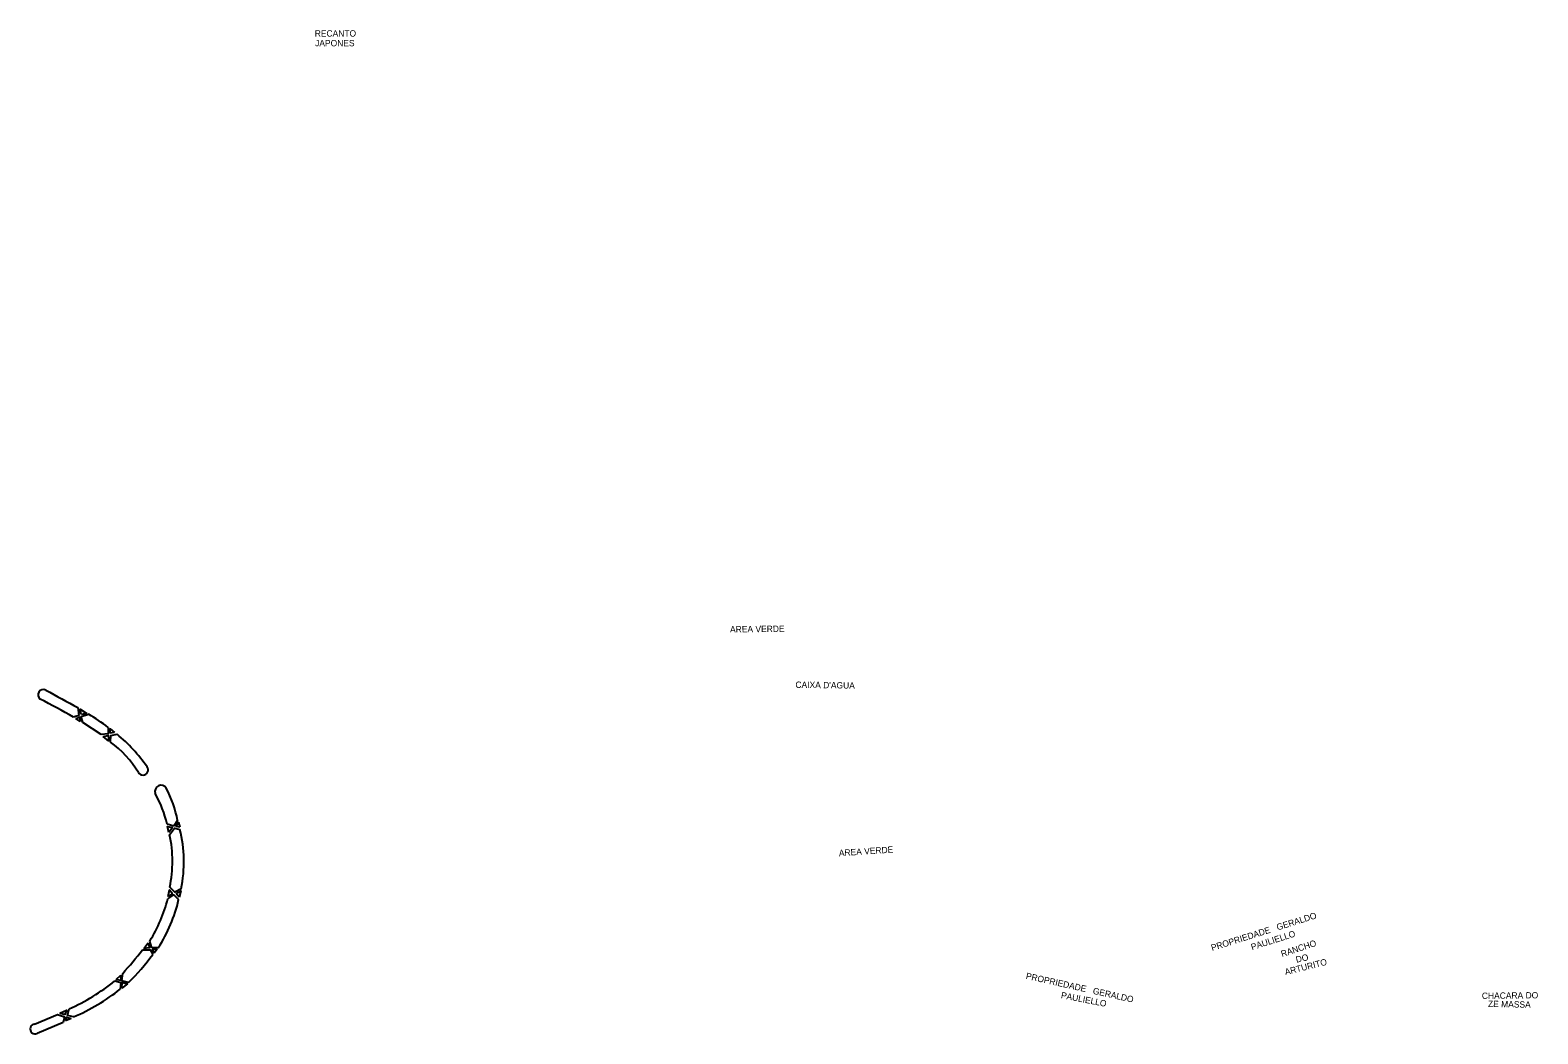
# Model space of a CAD drawing. Extents: x 325899 to 363134, y 7578590 to 7592502.
# Drawn here: x 338922 to 339876, y 7590627 to 7591261 of the extents above; entities that cross this region are included whole.
import ezdxf

# ---------------------------------------------------------------- set-up
doc = ezdxf.new("R2010")
doc.units = 0
doc.layers.add('EDIFIDENTIF', color=7, linetype='Continuous')
doc.layers.add('EDIFOBRAEXIS', color=7, linetype='Continuous')

msp = doc.modelspace()

# ---------------------------------------------------------------- linework, layer by layer
at = {"layer": 'EDIFOBRAEXIS'}
for points in [[(338952.27, 7590832.86), (338952.92, 7590827.89)], [(338954.34, 7590828.56), (338953.68, 7590831.88), (338957.86, 7590829.15)], [(338952.92, 7590827.89), (338949.55, 7590826.85)], [(338951.08, 7590825.9), (338953.39, 7590826.75), (338953.76, 7590824.14)], [(338953.76, 7590824.14), (338951.08, 7590825.9)], [(338957.86, 7590829.15), (338954.34, 7590828.56)], [(338955.34, 7590823.49), (338954.47, 7590827.17), (338958.98, 7590828.6)], [(338967.12, 7590815.74), (338955.34, 7590823.49)], [(338971.4, 7590820.27), (338971.4, 7590816.21), (338967.12, 7590815.74)], [(338968.27, 7590814.51), (338971.36, 7590815.09), (338971.79, 7590811.69)], [(338971.79, 7590811.69), (338968.27, 7590814.51)], [(338972.75, 7590816.6), (338972.62, 7590819.44), (338975.51, 7590817.05)], [(338975.51, 7590817.05), (338972.75, 7590816.6)], [(338972.87, 7590811.07), (338973.11, 7590815.21), (338977.06, 7590815.97)], [(339013.06, 7590757.84), (339008.76, 7590759.02)], [(339009.84, 7590753.86), (339008.95, 7590757.63), (339012.13, 7590756.92)], [(339012.13, 7590756.92), (339009.84, 7590753.86)], [(339010.33, 7590752.44), (339013.47, 7590756.62), (339016.8, 7590755.81)], [(339015.39, 7590761.54), (339013.06, 7590757.84)], [(339014.33, 7590757.72), (339015.93, 7590760.25), (339016.69, 7590757.23)], [(339016.69, 7590757.23), (339014.33, 7590757.72)], [(339009.49, 7590713.46), (339010.17, 7590717.65), (339012.14, 7590715.23)], [(339012.14, 7590715.23), (339009.49, 7590713.46)], [(339017.6, 7590718.24), (339013.56, 7590716.05), (339010.44, 7590719.23)], [(339014.5, 7590715.32), (339017.38, 7590716.92), (339016.45, 7590712.98)], [(339016.45, 7590712.98), (339014.5, 7590715.32)], [(339009.15, 7590711.88), (339012.99, 7590714.32), (339016.03, 7590711.38)], [(338993.21, 7590679.54), (338998.11, 7590679.65), (338999.6, 7590676.77)], [(338996.7, 7590684.04), (338997.61, 7590680.92), (338994.06, 7590680.48)], [(338994.06, 7590680.48), (338996.7, 7590684.04)], [(338999.06, 7590680.9), (338997.81, 7590685.21)], [(339003.17, 7590680.98), (338999.06, 7590680.9)], [(339000.58, 7590677.59), (338999.42, 7590679.86), (339002.34, 7590680.04)], [(339002.34, 7590680.04), (339000.58, 7590677.59)], [(338975.57, 7590659.97), (338979.41, 7590659.01), (338979.11, 7590654.74)], [(338979.43, 7590663.57), (338979.43, 7590660.25), (338976.48, 7590660.91)], [(338976.48, 7590660.91), (338979.43, 7590663.57)], [(338980.07, 7590655.46), (338980.32, 7590658.89), (338983.58, 7590658.12)], [(338983.58, 7590658.12), (338980.07, 7590655.46)], [(338980.19, 7590659.95), (338980.63, 7590664.77)], [(338984.33, 7590658.92), (338980.19, 7590659.95)], [(338940.79, 7590639.53), (338945.16, 7590641.54), (338944.12, 7590638.56)], [(338944.12, 7590638.56), (338940.79, 7590639.53)], [(338945.65, 7590638.19), (338946.83, 7590642.26)], [(338924.76, 7590632.73), (338939.35, 7590638.73), (338943.83, 7590637.19)], [(338942.89, 7590633.73), (338926.55, 7590626.81)], [(338943.83, 7590637.19), (338942.89, 7590633.73)], [(338944.46, 7590634.68), (338945.05, 7590637), (338948.07, 7590636.18)], [(338948.07, 7590636.18), (338944.46, 7590634.68)], [(338949.51, 7590637.21), (338945.65, 7590638.19)]]:
    msp.add_lwpolyline(points, dxfattribs=at)
for centre, radius, start, end in [((338930.55, 7590840.88), 3.36, 64.64355, 232.59308), ((339558.85, 7591969.39), 1288.27, 240.8833, 241.91073), ((338496.5, 7590012.57), 931.83, 60.90934, 62.37983), ((338904.38, 7590733.75), 109.44, 52.23856, 60.07378), ((338934.71, 7590758.23), 65.17, 30.99159, 54.16137), ((338909.24, 7590734.27), 106.19, 35.08974, 50.30164), ((338993.42, 7590793.45), 3.29, 210.17261, 34.57955), ((339004.91, 7590779.81), 3.92, 32.80975, 199.02784), ((338936.46, 7590745.19), 80.6, 11.69695, 27.11471), ((338934.41, 7590741.43), 76.41, 13.31512, 29.04992), ((338935.6, 7590735.3), 83.75, 348.24817, 14.17802), ((338931.97, 7590735.59), 80.15, 348.21967, 12.13387), ((338914.04, 7590736.56), 98.26, 328.48821, 345.45343), ((338920.75, 7590733.77), 97.88, 327.36126, 346.77331), ((338797.18, 7590833.77), 249.43, 317.35023, 321.80555), ((338890.08, 7590754.96), 134.57, 314.46207, 324.47571), ((338890.47, 7590765.95), 135.93, 294.49976, 308.7645), ((338897.39, 7590758.97), 132.45, 293.17247, 308.09754), ((338925.23, 7590629.64), 3.13, 98.74937, 294.98802)]:
    msp.add_arc(centre, radius, start, end, dxfattribs=at)

# ---------------------------------------------------------------- texts
at = {"layer": 'EDIFIDENTIF'}
for s, p in [('RECANTO', (339102.13, 7591257.17)), ('JAPONES', (339102.33, 7591251.04))]:
    msp.add_text(s, height=4, dxfattribs=at).set_placement(p)
for s, rotation, p in [('AREA VERDE', 0.66776, (339364.82, 7590880.32)), ("CAIXA D'AGUA", 359.20153, (339406.13, 7590845.33)), ('AREA VERDE', 3.9489, (339433.74, 7590738.8)), ('PROPRIEDADE   GERALDO', 17.38299, (339669.76, 7590678.9)), ('PAULIELLO', 17.63877, (339694.98, 7590679.35)), ('RANCHO', 18.22707, (339713.98, 7590675)), ('ARTURITO', 14.15039, (339716.17, 7590663.59)), ('DO', 12.22069, (339723.07, 7590671.48)), ('PROPRIEDADE   GERALDO', 347.43927, (339551.63, 7590661.34)), ('PAULIELLO', 349.0303, (339573.87, 7590649.11)), ('CHACARA DO', 0.60217, (339840.34, 7590648.57)), ('ZE MASSA', 358.90668, (339844.16, 7590643.51))]:
    msp.add_text(s, height=4, rotation=rotation, dxfattribs=at).set_placement(p)

doc.saveas('drawing.dxf')
